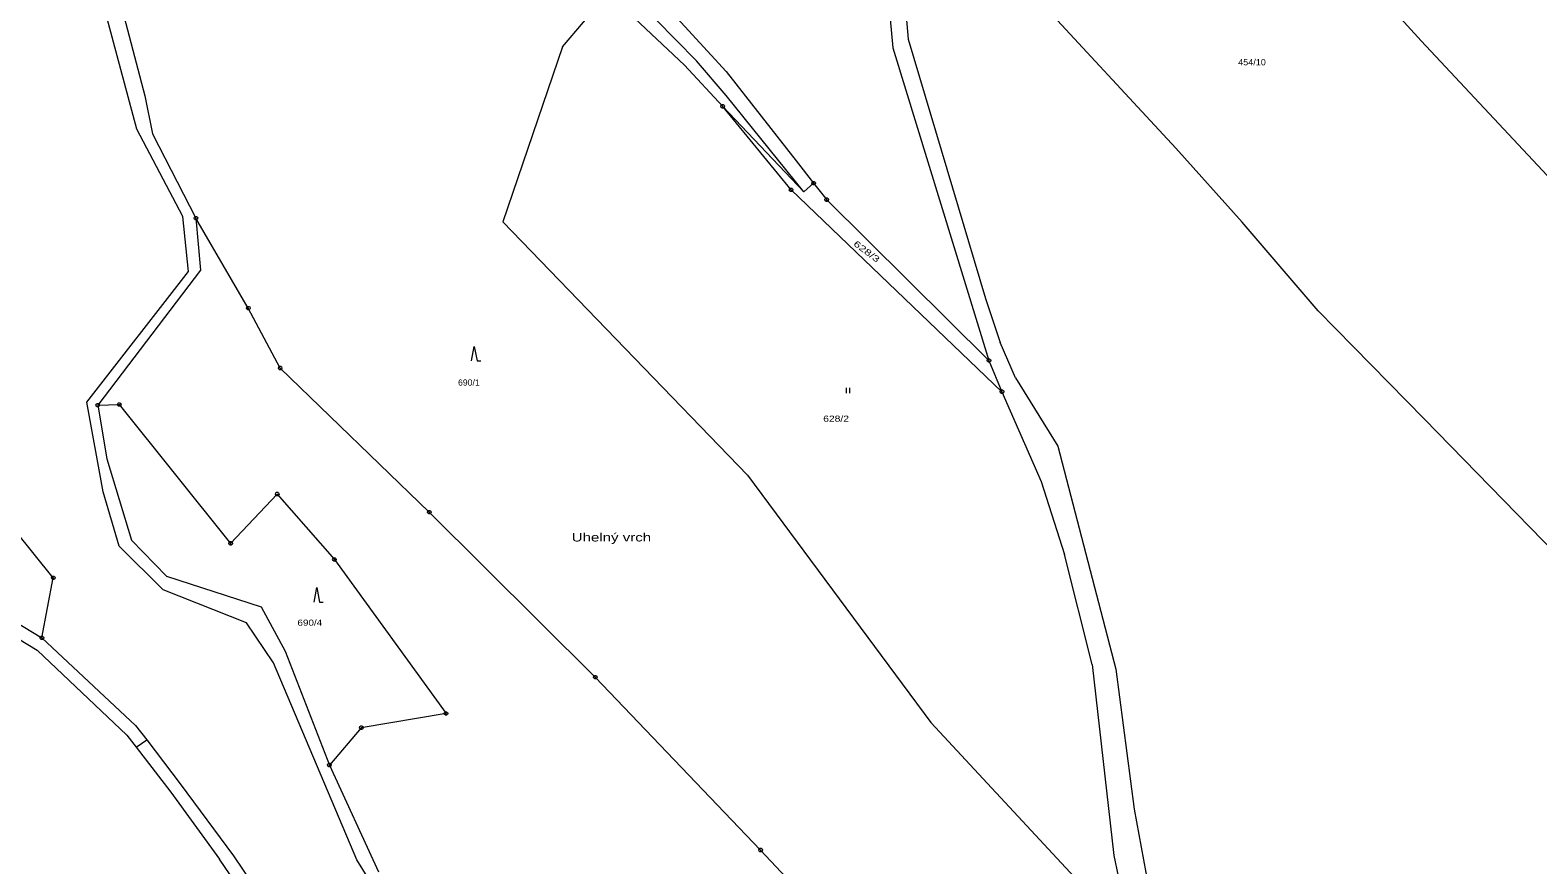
# Model space of a CAD drawing. Extents: x -687390 to -684106, y -954833 to -951648.
# Drawn here: x -686740.5 to -686324.4, y -953988.7 to -953758.4 of the extents above; entities that cross this region are included whole.
import ezdxf

# ---------------------------------------------------------------- set-up
doc = ezdxf.new("R2010")
doc.units = 0
doc.header["$LTSCALE"] = 0.68
for name, color, linetype, lineweight in [('1', 7, 'Continuous', 13), ('3', 7, 'Continuous', 13), ('7', 7, 'Continuous', 13), ('8', 7, 'Continuous', 13)]:
    doc.layers.add(name, color=color, linetype=linetype, lineweight=lineweight)
doc.layers.add('2', color=7, linetype='Continuous')

msp = doc.modelspace()

# ---------------------------------------------------------------- linework, layer by layer
at = {"layer": '1'}
for p, q in [((-686593.6, -953763.02), (-686580.97, -953748.25)), ((-686580.97, -953748.25), (-686559.93, -953768.1)), ((-686424.31, -953790.96), (-686464.34, -953747.72)), ((-686711.06, -953785.71), (-686719.91, -953752.77)), ((-686549.32, -953779.44), (-686559.93, -953768.1)), ((-686526.99, -953803), (-686549.32, -953779.44)), ((-686424.31, -953790.96), (-686406.02, -953811.37)), ((-686529.04, -953794.51), (-686524.24, -953800.63)), ((-686526.99, -953803), (-686524.24, -953800.63)), ((-686476.81, -953832.43), (-686472.76, -953844.58)), ((-686468.54, -953854.35), (-686472.76, -953844.58)), ((-686461.44, -953882.94), (-686454.99, -953903.05)), ((-686447.37, -953933.46), (-686454.99, -953903.05)), ((-686711.22, -953956.26), (-686708.25, -953954.21)), ((-686701.69, -953968.67), (-686688.23, -953987.18)), ((-686699.05, -953966.41), (-686684.36, -953986.27)), ((-686435.8, -953973.36), (-686429.32, -954008.64)), ((-686684.36, -953986.27), (-686647.65, -954040.42)), ((-686652.64, -954038.79), (-686688.23, -953987.18))]:
    msp.add_line(p, q, dxfattribs=at)
for points in [[(-686668.09, -953362.17), (-686619.01, -953408.19), (-686585.47, -953440.72), (-686527.74, -953502.84), (-686512.43, -953524.7), (-686497.96, -953546.57), (-686474.83, -953588.05), (-686464.57, -953611.24), (-686441.59, -953662.54), (-686423.97, -953687.37), (-686356.56, -953761.37), (-686286.97, -953835.75), (-686227.9, -953892.93), (-686194.98, -953922.35)], [(-686839.79, -953489.19), (-686849.5, -953511.8), (-686851.99, -953538.73), (-686842.1, -953560.06), (-686816.44, -953578.15), (-686785.17, -953591.65), (-686735.45, -953601.12), (-686703.86, -953620.79), (-686657.58, -953631.09), (-686629.18, -953645.02), (-686610.63, -953664.49), (-686593.4, -953691.27), (-686585.18, -953724.8), (-686575.37, -953740.35), (-686548.41, -953769.8), (-686529.04, -953794.51)], [(-686739.68, -953654.27), (-686735.65, -953660.78), (-686730.13, -953675.22), (-686728.66, -953702.36), (-686718.36, -953739.98), (-686708.78, -953776.54), (-686706.74, -953786.99), (-686694.74, -953810.32), (-686693.5, -953824.64), (-686721.8, -953861.89)], [(-686526.99, -953803), (-686548.4, -953776.46), (-686556.56, -953766.92), (-686579.05, -953743.94), (-686588.91, -953729.15), (-686599.46, -953693.05), (-686613, -953665.66), (-686625.26, -953657.03)], [(-686495.55, -953709.63), (-686497.24, -953713.89), (-686500.73, -953731.26), (-686498.12, -953760.92), (-686476.81, -953832.43)], [(-686505.48, -953729.57), (-686502.4, -953763.32), (-686475.85, -953849.59), (-686472.27, -953858.17), (-686461.44, -953882.94)], [(-686593.6, -953763.02), (-686610.03, -953811.28), (-686542.53, -953881.21), (-686491.9, -953949.46)], [(-686472.27, -953858.17), (-686530.45, -953802.48), (-686549.32, -953779.44)], [(-686724.86, -953861.07), (-686696.76, -953825.02), (-686698.37, -953809.86), (-686711.06, -953785.71)], [(-686524.24, -953800.63), (-686520.65, -953805.19), (-686475.85, -953849.59)], [(-686413.2, -954108.29), (-686446.13, -954078.52), (-686520.3, -954004.42), (-686538.89, -953984.63), (-686584.5, -953936.92), (-686630.31, -953891.41), (-686671.47, -953851.65), (-686680.28, -953835.1), (-686694.74, -953810.32)], [(-686240.39, -953985.84), (-686275.53, -953947.89), (-686355.72, -953865.7), (-686384.99, -953835.84), (-686406.02, -953811.37)], [(-686737.23, -953926.12), (-686734.1, -953909.55), (-686755.19, -953883.45), (-686764.66, -953867.33), (-686774.54, -953844.47), (-686782.36, -953824.42)], [(-686782.76, -953847.44), (-686777.57, -953873.55), (-686760.56, -953912.04), (-686737.23, -953926.12), (-686711.36, -953950.25)], [(-686468.54, -953854.35), (-686456.88, -953873.17), (-686440.87, -953934.73), (-686435.8, -953973.36)], [(-686625.98, -954026.58), (-686650.34, -953987.3), (-686673.27, -953932.99), (-686680.76, -953921.95), (-686703.81, -953912.83), (-686715.91, -953900.78), (-686720.34, -953885.8), (-686724.86, -953861.07)], [(-686721.8, -953861.89), (-686715.9, -953861.72), (-686685.15, -953900.03), (-686672.29, -953886.41), (-686656.48, -953904.5), (-686625.7, -953946.97), (-686649.08, -953950.89), (-686657.88, -953961.18)], [(-686721.8, -953861.89), (-686719.33, -953876.68), (-686712.55, -953899.17), (-686702.88, -953909.09), (-686676.69, -953917.54), (-686670.12, -953929.75), (-686657.88, -953961.18), (-686644.32, -953990.68)], [(-686780.61, -953874.29), (-686775.09, -953887.27), (-686762.3, -953915.12), (-686738.54, -953929.49), (-686713.79, -953952.9)], [(-686447.37, -953933.46), (-686441.4, -953986.17), (-686436.59, -954008.97), (-686491.9, -953949.46)], [(-686713.79, -953952.9), (-686711.22, -953956.26), (-686701.69, -953968.67)], [(-686711.36, -953950.25), (-686708.25, -953954.21), (-686699.05, -953966.41)]]:
    msp.add_lwpolyline(points, dxfattribs=at)
at = {"layer": '3'}
for p, q in [((-686515.26, -953857.12), (-686515.26, -953858.62)), ((-686514.26, -953858.62), (-686514.26, -953857.12))]:
    msp.add_line(p, q, dxfattribs=at)
for points in [[(-686618.64, -953849.68), (-686617.89, -953845.68), (-686617.14, -953849.68), (-686616.14, -953849.68)], [(-686662.12, -953916.23), (-686661.37, -953912.23), (-686660.62, -953916.23), (-686659.62, -953916.23)]]:
    msp.add_lwpolyline(points, dxfattribs=at)
at = {"layer": '8'}
for p, q in [((-686549.44, -953779.44), (-686549.2, -953779.44)), ((-686530.57, -953802.48), (-686530.33, -953802.48)), ((-686524.36, -953800.63), (-686524.12, -953800.63)), ((-686520.77, -953805.19), (-686520.53, -953805.19)), ((-686694.86, -953810.32), (-686694.62, -953810.32)), ((-686680.4, -953835.1), (-686680.16, -953835.1)), ((-686671.59, -953851.65), (-686671.35, -953851.65)), ((-686475.97, -953849.59), (-686475.73, -953849.59)), ((-686716.02, -953861.72), (-686715.78, -953861.72)), ((-686472.39, -953858.17), (-686472.15, -953858.17)), ((-686721.92, -953861.89), (-686721.68, -953861.89)), ((-686672.41, -953886.41), (-686672.17, -953886.41)), ((-686630.43, -953891.41), (-686630.19, -953891.41)), ((-686685.27, -953900.03), (-686685.03, -953900.03)), ((-686656.6, -953904.5), (-686656.36, -953904.5)), ((-686734.22, -953909.55), (-686733.98, -953909.55)), ((-686737.35, -953926.12), (-686737.11, -953926.12)), ((-686584.62, -953936.92), (-686584.38, -953936.92)), ((-686625.82, -953946.97), (-686625.58, -953946.97)), ((-686649.2, -953950.89), (-686648.96, -953950.89)), ((-686658, -953961.18), (-686657.76, -953961.18)), ((-686539.01, -953984.63), (-686538.77, -953984.63))]:
    msp.add_line(p, q, dxfattribs=at)
for points in [[(-686549.17, -953778.96), (-686548.92, -953779.14), (-686548.82, -953779.43), (-686548.92, -953779.72), (-686549.17, -953779.9), (-686549.48, -953779.9), (-686549.73, -953779.72), (-686549.83, -953779.43), (-686549.73, -953779.14), (-686549.48, -953778.96)], [(-686530.3, -953802), (-686530.05, -953802.18), (-686529.95, -953802.47), (-686530.05, -953802.76), (-686530.3, -953802.94), (-686530.61, -953802.94), (-686530.86, -953802.76), (-686530.96, -953802.47), (-686530.86, -953802.18), (-686530.61, -953802)], [(-686524.09, -953800.15), (-686523.84, -953800.33), (-686523.74, -953800.62), (-686523.84, -953800.91), (-686524.09, -953801.09), (-686524.4, -953801.09), (-686524.65, -953800.91), (-686524.75, -953800.62), (-686524.65, -953800.33), (-686524.4, -953800.15)], [(-686520.5, -953804.71), (-686520.25, -953804.89), (-686520.15, -953805.18), (-686520.25, -953805.47), (-686520.5, -953805.65), (-686520.81, -953805.65), (-686521.06, -953805.47), (-686521.16, -953805.18), (-686521.06, -953804.89), (-686520.81, -953804.71)], [(-686694.59, -953809.84), (-686694.34, -953810.02), (-686694.24, -953810.31), (-686694.34, -953810.6), (-686694.59, -953810.78), (-686694.9, -953810.78), (-686695.15, -953810.6), (-686695.25, -953810.31), (-686695.15, -953810.02), (-686694.9, -953809.84)], [(-686680.13, -953834.62), (-686679.88, -953834.8), (-686679.78, -953835.09), (-686679.88, -953835.38), (-686680.13, -953835.56), (-686680.44, -953835.56), (-686680.69, -953835.38), (-686680.79, -953835.09), (-686680.69, -953834.8), (-686680.44, -953834.62)], [(-686475.7, -953849.11), (-686475.45, -953849.29), (-686475.35, -953849.58), (-686475.45, -953849.87), (-686475.7, -953850.05), (-686476.01, -953850.05), (-686476.26, -953849.87), (-686476.36, -953849.58), (-686476.26, -953849.29), (-686476.01, -953849.11)], [(-686671.32, -953851.17), (-686671.07, -953851.35), (-686670.97, -953851.64), (-686671.07, -953851.93), (-686671.32, -953852.11), (-686671.63, -953852.11), (-686671.88, -953851.93), (-686671.98, -953851.64), (-686671.88, -953851.35), (-686671.63, -953851.17)], [(-686721.65, -953861.41), (-686721.4, -953861.59), (-686721.3, -953861.88), (-686721.4, -953862.17), (-686721.65, -953862.35), (-686721.96, -953862.35), (-686722.21, -953862.17), (-686722.31, -953861.88), (-686722.21, -953861.59), (-686721.96, -953861.41)], [(-686715.75, -953861.24), (-686715.5, -953861.42), (-686715.4, -953861.71), (-686715.5, -953862), (-686715.75, -953862.18), (-686716.06, -953862.18), (-686716.31, -953862), (-686716.41, -953861.71), (-686716.31, -953861.42), (-686716.06, -953861.24)], [(-686472.12, -953857.69), (-686471.87, -953857.87), (-686471.77, -953858.16), (-686471.87, -953858.45), (-686472.12, -953858.63), (-686472.43, -953858.63), (-686472.68, -953858.45), (-686472.78, -953858.16), (-686472.68, -953857.87), (-686472.43, -953857.69)], [(-686672.14, -953885.93), (-686671.89, -953886.11), (-686671.79, -953886.4), (-686671.89, -953886.69), (-686672.14, -953886.87), (-686672.45, -953886.87), (-686672.7, -953886.69), (-686672.8, -953886.4), (-686672.7, -953886.11), (-686672.45, -953885.93)], [(-686630.16, -953890.93), (-686629.91, -953891.11), (-686629.81, -953891.4), (-686629.91, -953891.69), (-686630.16, -953891.87), (-686630.47, -953891.87), (-686630.72, -953891.69), (-686630.82, -953891.4), (-686630.72, -953891.11), (-686630.47, -953890.93)], [(-686685, -953899.55), (-686684.75, -953899.73), (-686684.65, -953900.02), (-686684.75, -953900.31), (-686685, -953900.49), (-686685.31, -953900.49), (-686685.56, -953900.31), (-686685.66, -953900.02), (-686685.56, -953899.73), (-686685.31, -953899.55)], [(-686656.33, -953904.02), (-686656.08, -953904.2), (-686655.98, -953904.49), (-686656.08, -953904.78), (-686656.33, -953904.96), (-686656.64, -953904.96), (-686656.89, -953904.78), (-686656.99, -953904.49), (-686656.89, -953904.2), (-686656.64, -953904.02)], [(-686733.95, -953909.07), (-686733.7, -953909.25), (-686733.6, -953909.54), (-686733.7, -953909.83), (-686733.95, -953910.01), (-686734.26, -953910.01), (-686734.51, -953909.83), (-686734.61, -953909.54), (-686734.51, -953909.25), (-686734.26, -953909.07)], [(-686737.08, -953925.64), (-686736.83, -953925.82), (-686736.73, -953926.11), (-686736.83, -953926.4), (-686737.08, -953926.58), (-686737.39, -953926.58), (-686737.64, -953926.4), (-686737.74, -953926.11), (-686737.64, -953925.82), (-686737.39, -953925.64)], [(-686584.35, -953936.44), (-686584.1, -953936.62), (-686584, -953936.91), (-686584.1, -953937.2), (-686584.35, -953937.38), (-686584.66, -953937.38), (-686584.91, -953937.2), (-686585.01, -953936.91), (-686584.91, -953936.62), (-686584.66, -953936.44)], [(-686625.55, -953946.49), (-686625.3, -953946.67), (-686625.2, -953946.96), (-686625.3, -953947.25), (-686625.55, -953947.43), (-686625.86, -953947.43), (-686626.11, -953947.25), (-686626.21, -953946.96), (-686626.11, -953946.67), (-686625.86, -953946.49)], [(-686648.93, -953950.41), (-686648.68, -953950.59), (-686648.58, -953950.88), (-686648.68, -953951.17), (-686648.93, -953951.35), (-686649.24, -953951.35), (-686649.49, -953951.17), (-686649.59, -953950.88), (-686649.49, -953950.59), (-686649.24, -953950.41)], [(-686657.73, -953960.7), (-686657.48, -953960.88), (-686657.38, -953961.17), (-686657.48, -953961.46), (-686657.73, -953961.64), (-686658.04, -953961.64), (-686658.29, -953961.46), (-686658.39, -953961.17), (-686658.29, -953960.88), (-686658.04, -953960.7)], [(-686538.74, -953984.15), (-686538.49, -953984.33), (-686538.39, -953984.62), (-686538.49, -953984.91), (-686538.74, -953985.09), (-686539.05, -953985.09), (-686539.3, -953984.91), (-686539.4, -953984.62), (-686539.3, -953984.33), (-686539.05, -953984.15)]]:
    msp.add_lwpolyline(points, close=True, dxfattribs=at)

# ---------------------------------------------------------------- texts
at = {"layer": '2'}
for s, width, p in [('454/10', 1.1, (-686407.085, -953768.11)), ('690/1', 1.05, (-686622.386, -953856.49)), ('628/2', 1.25, (-686521.606, -953866.47)), ('690/4', 1.2, (-686666.706, -953922.75))]:
    msp.add_text(s, height=1.7, dxfattribs=dict(at, width=width)).set_placement(p)
at = {"layer": '2', "width": 1.45}
msp.add_text('628/3', height=1.7, rotation=323.091, dxfattribs=at).set_placement((-686513.419, -953817.679))
at = {"layer": '7', "width": 1.35}
msp.add_text('Uhelný vrch', height=2.3, dxfattribs=at).set_placement((-686591.014, -953899.5))

doc.saveas('drawing.dxf')
